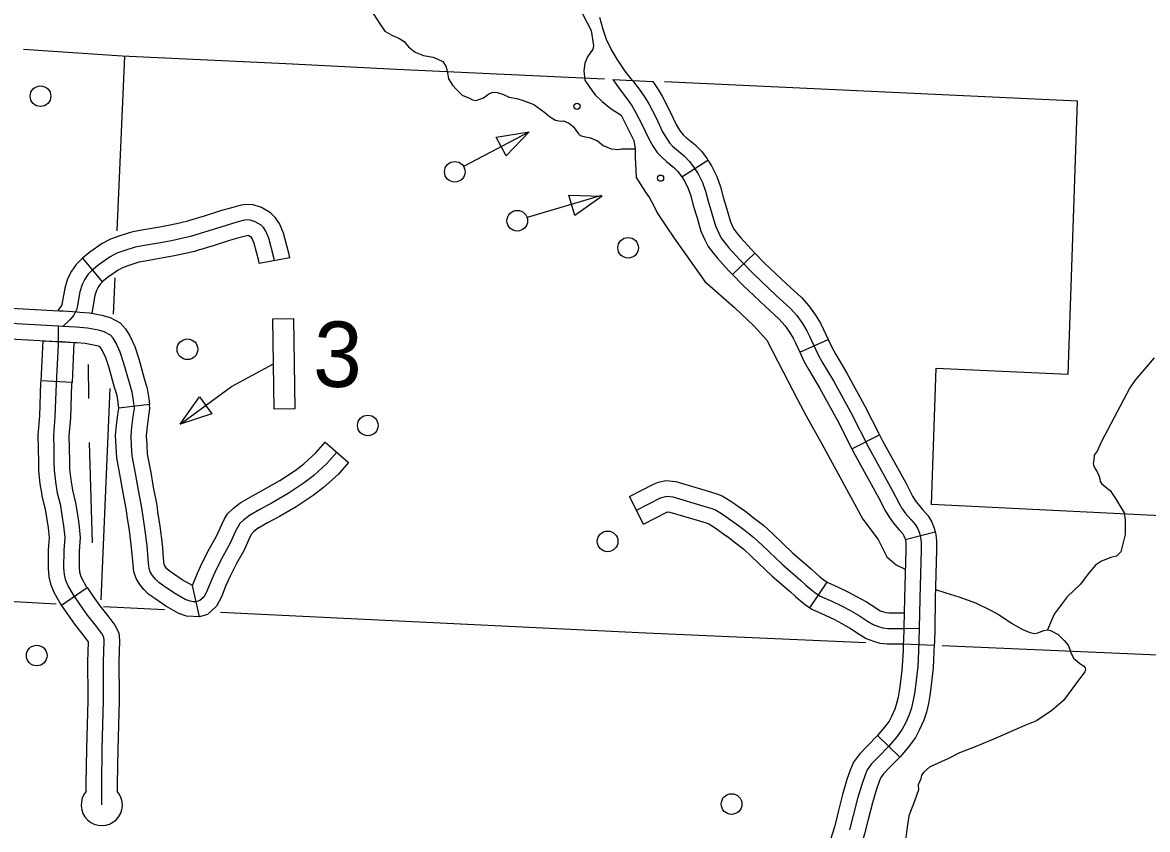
# Model space of a CAD drawing. Extents: x 653372 to 905732, y 627442 to 787275.
# Drawn here: x 699755 to 705201, y 751385 to 755293 of the extents above; entities that cross this region are included whole.
import ezdxf

# ---------------------------------------------------------------- set-up
doc = ezdxf.new("R2010")
doc.units = 0
for name, color, linetype in [('31', 7, 'Continuous'), ('32', 7, 'Continuous'), ('33', 7, 'Continuous'), ('35', 7, 'Continuous'), ('45', 7, 'Continuous'), ('5', 7, 'Continuous'), ('56', 7, 'Continuous'), ('6', 7, 'Continuous')]:
    doc.layers.add(name, color=color, linetype=linetype)

msp = doc.modelspace()

# ---------------------------------------------------------------- linework, layer by layer
at = {"layer": '31'}
for p, q in [((700018.9, 753741.3), (700018.9, 753741.3)), ((699994.9, 753549.8), (699845.1, 753557.1)), ((699994.9, 753549.8), (699994.9, 753549.8)), ((700369.9, 753442.9), (700220.9, 753425.8)), ((701221, 753261.2), (701333.7, 753162.2)), ((699944.5, 752471.2), (700067.8, 752556.6)), ((700611.3, 752414), (700578.1, 752565.9))]:
    msp.add_line(p, q, dxfattribs=at)
for points in [[(699501.8, 753919.4), (699641.5, 753913), (699931.6, 753896.4), (699952.7, 753896.2), (700020.2, 753891.8), (700032.3, 753890.7)], [(700032.3, 753890.7), (700079.2, 753886.4), (700139.9, 753875.5), (700179.4, 753864.9), (700228.6, 753837.7), (700254.4, 753808.6), (700274.1, 753775.8), (700298.6, 753723), (700317.7, 753663.9), (700344.5, 753568.2), (700359.3, 753519.9), (700366.5, 753472.7), (700369.9, 753442.9)], [(699929, 753821.5), (699637.6, 753838.1), (699423.8, 753847.8), (699374.8, 753852.6), (699363, 753857.6)], [(700139.1, 751504.1), (700138.7, 751606.3), (700141.4, 751773.3), (700147.3, 752009.2), (700147.1, 752196.1), (700150.2, 752298.1), (700148.4, 752315.6), (700138.5, 752334.4), (700108.3, 752373.7), (700069.2, 752423.6), (700035.8, 752471), (700001.4, 752520.8), (699976, 752565.6), (699965.2, 752590.3), (699959.1, 752619.5), (699955.4, 752652.2), (699956.8, 752736.2), (699961, 752798.8), (699955.7, 752855.8), (699946.8, 752907.2), (699940, 752951.5), (699924.5, 753013.4), (699915.7, 753068.3), (699909.3, 753125.3), (699909.2, 753161.3), (699907.9, 753232.5), (699906.2, 753292.9), (699913.6, 753383.2), (699919.6, 753544.3), (699928.7, 753732.1), (699929, 753821.5)], [(701277.3, 753211.7), (701228.9, 753156.5), (701164.8, 753098.5), (701117.8, 753063), (701040.8, 753011.2), (700963.2, 752966.7), (700904.8, 752934.8), (700853.3, 752905.5), (700826.4, 752885), (700807, 752865.9), (700798.4, 752852.2), (700787, 752829.5), (700760.7, 752772.1), (700725.1, 752707.5), (700692.9, 752644.2), (700670.9, 752596.5), (700649.7, 752542.9), (700634, 752512.2), (700612.9, 752493.2), (700596.3, 752487.9), (700583.2, 752486.7), (700566.1, 752491.3), (700543.3, 752499.4), (700488.1, 752530.6), (700438.3, 752564.9), (700415, 752581.2), (700398.2, 752597.3), (700384.8, 752614.1), (700373.8, 752632.5), (700367.8, 752649.1), (700365.3, 752674.6), (700357.9, 752758.5), (700346.6, 752843.9), (700332.3, 752942.8), (700316, 753028.6), (700303.4, 753101.2), (700286.5, 753193.8), (700283.1, 753243.1), (700280.4, 753290.8), (700284.1, 753332.5), (700291.4, 753384.8), (700296.7, 753423.2), (700292.1, 753462.8), (700286, 753503.1), (700272.5, 753547), (700245.8, 753642.2), (700228.6, 753695.7), (700207.8, 753740.6), (700193.7, 753764), (700181, 753778.3), (700151.2, 753794.8), (700123.5, 753802.2), (700069.2, 753812), (700014.3, 753817), (699949.8, 753821.2), (699929, 753821.5)], [(700018.9, 753741.3), (700008.5, 753742.2), (699946.9, 753746.3), (699926.5, 753746.5), (699633.8, 753763.2), (699495, 753769.5)], [(699845.1, 753557.1), (699854.5, 753750.6), (700004.3, 753742.6)], [(700004.3, 753742.6), (699994.9, 753549.8)], [(700220.9, 753425.8), (700217.8, 753452.8), (700212.7, 753486.4), (700200.5, 753525.9), (700174, 753620.6), (700158.6, 753668.3), (700141.4, 753705.4), (700133.2, 753719), (700122.9, 753724.7), (700107.1, 753729), (700059.1, 753737.6), (700018.9, 753741.3)], [(699848.3, 753014.9), (699841.4, 753058.1), (699834.3, 753121), (699834.2, 753160.5), (699832.9, 753230.7), (699831.1, 753294.9), (699838.7, 753387.6), (699844.6, 753547.6), (699845.1, 753557.1)], [(699996.4, 753038.7), (699990, 753078.4), (699984.3, 753129.6), (699984.2, 753162.1), (699982.9, 753234.2), (699981.3, 753290.9), (699988.5, 753378.8), (699994.5, 753541.1), (699994.9, 753549.8)], [(700262.5, 752901.4), (700258.3, 752930.4), (700242.2, 753015.2), (700229.6, 753088), (700212, 753184.4), (700208.2, 753238.4), (700205.2, 753292), (700209.6, 753341), (700217.1, 753395.1), (700221.1, 753424), (700220.9, 753425.8)], [(700411, 752922.8), (700406.3, 752955.1), (700389.8, 753042), (700377.3, 753114.3), (700361, 753203.1), (700357.9, 753247.8), (700355.6, 753289.6), (700358.7, 753324), (700365.7, 753374.5), (700372.3, 753422.4), (700369.9, 753443)], [(700806.8, 752964.4), (700811.8, 752968.2), (700868.3, 753000.3), (700926.6, 753032.2), (701001.2, 753074.9), (701074.3, 753124.1), (701117, 753156.4), (701175.4, 753209.2), (701221, 753261.2)], [(701333.7, 753162.2), (701282.4, 753103.8), (701212.7, 753040.7), (701161.4, 753002), (701080.4, 752947.4), (700999.8, 752901.3), (700941.3, 752869.4), (700894.8, 752842.8), (700897.9, 752845.2)], [(699944.5, 752471.2), (699937.8, 752480.9), (699908.9, 752532), (699893.4, 752567.4), (699884.9, 752607.7), (699880.4, 752648.6), (699881.8, 752739.4), (699885.8, 752797.9), (699881.3, 752846), (699872.8, 752895.1), (699866.4, 752936.6), (699851, 752998.3), (699848.3, 753014.9)], [(700067.8, 752556.6), (700065, 752560.7), (700043.2, 752599.3), (700037, 752613.3), (700033.2, 752631.4), (700030.5, 752655.7), (700031.7, 752733.1), (700036.2, 752799.7), (700030.1, 752865.7), (700020.9, 752919.2), (700013.7, 752966.3), (699998, 753028.5), (699996.4, 753038.7)], [(700578.1, 752565.9), (700602, 752626), (700625.4, 752676.9), (700658.9, 752742.6), (700693.7, 752805.8), (700719.4, 752862), (700733, 752889), (700748.2, 752913.2), (700777.2, 752941.7), (700806.8, 752964.4)], [(700611.3, 752414), (700549.1, 752418.2), (700543.7, 752419.6), (700512.1, 752430.9), (700448.3, 752466.9), (700395.5, 752503.3), (700367.2, 752523), (700342.7, 752546.6), (700323, 752571.3), (700305.8, 752600.1), (700294.1, 752632.2), (700290.6, 752667.6), (700283.4, 752750.3), (700272.3, 752833.6), (700262.5, 752901.4)], [(700578.1, 752565.9), (700527.9, 752594.2), (700481, 752626.5), (700462.7, 752639.3), (700453.7, 752647.9), (700446.6, 752656.9), (700441.9, 752664.8), (700441.5, 752665.9), (700439.9, 752681.5), (700432.5, 752766.7), (700420.8, 752854.2), (700411, 752922.8)], [(700897.9, 752845.2), (700875.7, 752828.2), (700865.8, 752818.5), (700863.8, 752815.3), (700854.7, 752797.1), (700827.7, 752738.3), (700791.4, 752672.4), (700760.4, 752611.5), (700739.9, 752566.9), (700718, 752511.9), (700694.5, 752465.8), (700651.1, 752426.6), (700611.3, 752414)], [(700067.8, 752556.6), (700097.3, 752513.9), (700129.5, 752468.3), (700167.6, 752419.6), (700201.9, 752375), (700221.5, 752337.6), (700225.3, 752300.8), (700222.1, 752195), (700222.3, 752032.1)], [(700072.3, 752031.9), (700072.1, 752197.2), (700075, 752294), (700049.1, 752327.7), (700009, 752378.8), (699974.3, 752428.1), (699944.5, 752471.2)], [(700063.8, 751570), (700063.7, 751606.7), (700066.4, 751774.9), (700072.3, 752010.1), (700072.3, 752031.9)], [(700222.3, 752032.1), (700222.3, 752008.3), (700216.3, 751771.8), (700213.7, 751605.8), (700213.8, 751570.6)]]:
    msp.add_lwpolyline(points, dxfattribs=at)
msp.add_arc((700139.1, 751504.1), 100, 138.822, 41.6419, dxfattribs=at)
at = {"layer": '32'}
for p, q in [((702612.7, 755016.6), (702806.1, 755007.6)), ((702946.6, 754544.6), (703072.2, 754626.6)), ((703192.3, 754072.4), (703300.7, 754176)), ((703518.4, 753696), (703654.8, 753758.3)), ((703769.6, 753228.3), (703903.3, 753296.2)), ((704027.9, 752788.7), (704173, 752826.7)), ((704018.7, 752283.5), (704168.6, 752277.1)), ((703893.5, 751840), (704001.3, 751735.6))]:
    msp.add_line(p, q, dxfattribs=at)
for points in [[(702612.7, 755016.6), (702648.1, 754966.1), (702684.5, 754919.4), (702705.6, 754887.1), (702721.5, 754861.3), (702755, 754797.2), (702787.2, 754728.7), (702808.8, 754691.9), (702827.7, 754663.7), (702849.4, 754639.8), (702872.8, 754620), (702907.4, 754591.1), (702927.1, 754571.3), (702945.4, 754546.5), (702946.6, 754544.6)], [(702707.3, 755012.2), (702745.6, 754963), (702768.9, 754927.3), (702786.7, 754898.4), (702822.2, 754830.5), (702853.6, 754763.7), (702872.4, 754731.8), (702886.9, 754710.1), (702901.6, 754693.9), (702921.1, 754677.4), (702958.1, 754646.4), (702984.2, 754620.3), (703007.1, 754589.3), (703025.9, 754560.3), (703047.4, 754518.2), (703061.8, 754475.2), (703074.6, 754426.7), (703092.5, 754367.9), (703109.5, 754307.6), (703125.1, 754272.2), (703137.1, 754249), (703156.1, 754224.7), (703174.6, 754201.3), (703228.1, 754143.5), (703294.8, 754073.6), (703402.2, 753972.9), (703472.1, 753908), (703503.5, 753873.1), (703531.2, 753834.8), (703551.9, 753800.3), (703565.3, 753773.8), (703605.2, 753686.6), (703626.3, 753647.4), (703680.2, 753557.5)], [(702806.1, 755007.6), (702832.2, 754967.5), (702852, 754935.5), (702889.4, 754863.8), (702920, 754798.8), (702935.9, 754771.7), (702946.1, 754756.4), (702953.8, 754748), (702969.4, 754734.8), (703008.9, 754701.8), (703041.3, 754669.3), (703068.7, 754632), (703072.2, 754626.6)], [(703072.2, 754626.6), (703090.9, 754598), (703116.8, 754547.3), (703133.8, 754496.6), (703146.7, 754447.2), (703164.5, 754389), (703180.2, 754333), (703192.8, 754304.6), (703200.5, 754289.7), (703215, 754271), (703231.6, 754250.2), (703282.7, 754194.9), (703300.7, 754176)], [(702946.6, 754544.6), (702960.9, 754522.7), (702978.1, 754489), (702989.9, 754453.7), (703002.4, 754406.2), (703020.6, 754346.8), (703038.7, 754282.2), (703057.4, 754239.8), (703073.6, 754208.4), (703097.1, 754178.3), (703117.6, 754152.5), (703173.4, 754092.1), (703192.3, 754072.4)], [(703300.7, 754176), (703347.6, 754126.9), (703453.3, 754027.7), (703525.6, 753960.7), (703561.9, 753920.3), (703593.8, 753876.2), (703617.6, 753836.6), (703632.9, 753806.4), (703654.8, 753758.3)], [(703192.3, 754072.4), (703242, 754020.3), (703351, 753918.1), (703418.6, 753855.3), (703445, 753826), (703468.5, 753793.5), (703486.2, 753764), (703497.7, 753741.3), (703518.4, 753696)], [(703654.8, 753758.3), (703672.4, 753720), (703691.5, 753684.5), (703745.2, 753594.8), (703831, 753438.7), (703903.3, 753296.2)], [(703518.4, 753696), (703538, 753653.1), (703561.1, 753610.3), (703615.1, 753520.1), (703698.4, 753368.6), (703769.6, 753228.3)], [(703680.2, 753557.5), (703764.7, 753403.6), (703851.6, 753232.4), (703965.6, 753027.7), (703998.2, 752963.4), (704014.1, 752937.1), (704030.1, 752914.7), (704055.1, 752885.8), (704077.9, 752859.8), (704088.8, 752840.5), (704097.4, 752819.5), (704102.5, 752799.8), (704105.3, 752776.7), (704105.3, 752738.5), (704098.8, 752504), (704096.2, 752359.5), (704094.3, 752295.1), (704092.3, 752248), (704088.9, 752172.7), (704086.4, 752148.3), (704079, 752092.7), (704072.9, 752044), (704067.3, 752010.8), (704058.2, 751974.2), (704047.4, 751940.6), (704028.9, 751899.2), (704013.7, 751870.4), (703987.3, 751833.3), (703948, 751788.4), (703898.1, 751737), (703864.9, 751702.3), (703844.5, 751674.2), (703832.4, 751645.1), (703817.4, 751603), (703796.9, 751534.6), (703776, 751452.4), (703759, 751383.9)], [(703903.3, 753296.2), (703917.8, 753267.7), (704031.8, 753062.9), (704063.8, 752999.8), (704076.8, 752978.3), (704089.1, 752961.2), (704111.7, 752935), (704139.4, 752903.4), (704156.4, 752873.2), (704168.7, 752843.3), (704173, 752826.7)], [(703769.6, 753228.3), (703785.3, 753197.2), (703899.4, 752992.5), (703932.5, 752927.1), (703951.4, 752895.8), (703971.1, 752868.3), (703998.5, 752836.5), (704016.4, 752816.1), (704021.2, 752807.7), (704026.1, 752795.7), (704027.9, 752788.7)], [(704173, 752826.7), (704176.4, 752813.8), (704180.3, 752781.1), (704180.3, 752737.5), (704173.8, 752502.2), (704171.2, 752357.7), (704169.2, 752292.4), (704168.6, 752277.1)], [(704027.9, 752788.7), (704028.7, 752785.8), (704030.3, 752772.2), (704030.3, 752739.5), (704023.9, 752505.7), (704021.2, 752361.3), (704019.3, 752297.8), (704018.7, 752283.5)], [(704018.7, 752283.5), (704017.4, 752251.3), (704014.1, 752178.2), (704011.9, 752157), (704004.6, 752102.3), (703998.7, 752054.9), (703993.9, 752026.2), (703986, 751994.8), (703977.3, 751967.5), (703961.5, 751932.1), (703949.7, 751909.9), (703928.3, 751879.8), (703892.8, 751839.3), (703893.6, 751840.1)], [(704168.6, 752277.1), (704167.2, 752244.7), (704163.7, 752167.3), (704160.9, 752139.6), (704153.4, 752083.1), (704147.2, 752033.1), (704140.8, 751995.4), (704130.4, 751953.7), (704117.6, 751913.8), (704096.4, 751866.3), (704077.6, 751831), (704046.2, 751786.7), (704003.1, 751737.5), (704001.2, 751735.6)], [(703893.5, 751840), (703844.1, 751789), (703807.1, 751750.5), (703778.5, 751711), (703762.4, 751672.1), (703746.1, 751626.4), (703724.6, 751554.6), (703703.3, 751470.6), (703686.6, 751403.3), (703667.1, 751336.1)], [(704001.3, 751735.6), (703952.1, 751684.9), (703922.6, 751654.1), (703910.4, 751637.3), (703902.4, 751618.1), (703888.6, 751579.6), (703869.2, 751514.6), (703848.8, 751434.1), (703831.5, 751364.4), (703811.2, 751294.5)]]:
    msp.add_lwpolyline(points, dxfattribs=at)
at = {"layer": '33'}
msp.add_lwpolyline([(702707.3, 755012.2), (702673.1, 755056.3), (702634.3, 755114.4), (702605.1, 755162.9), (702582.4, 755210.6), (702566, 755258), (702549.3, 755316.9)], dxfattribs=at)
at = {"layer": '35'}
for points in [[(702437, 755387.9), (702466.6, 755334.3), (702508.1, 755253.7), (702518.9, 755178.9), (702515.6, 755163), (702489.8, 755126.5), (702477.1, 755095.8), (702472.2, 755058.8), (702477.2, 755013.7), (702516.4, 754956.8), (702526.7, 754942.9)], [(701438.1, 755358.1), (701485.1, 755285.8), (701509.7, 755249.9), (701542.9, 755231.4), (701577.6, 755216.8), (701602.8, 755199.8), (701623.7, 755174.9), (701656.6, 755148.2), (701696.7, 755133.5), (701743.8, 755125.3), (701765.1, 755115.2), (701789.1, 755103.7), (701805.8, 755077.5), (701813.1, 755048.9), (701817.6, 755019), (701837, 754988.7), (701856.6, 754967.8), (701884.2, 754941.3), (701918.9, 754926.8), (701933.5, 754918.2), (701950.9, 754915), (701986.5, 754927.4), (702012.7, 754946.9), (702031.9, 754954.5), (702053.5, 754953.8), (702084.2, 754943.4), (702110.9, 754930.5), (702148.5, 754923.9), (702179.3, 754914.9), (702230.1, 754895.8), (702282.9, 754856.4), (702305.4, 754838.1), (702335.9, 754819.6), (702358.7, 754814.9), (702373.6, 754817.1), (702399, 754805.6), (702404.2, 754801.4), (702420.1, 754788.7), (702433, 754770.8), (702446.1, 754754.1), (702455.3, 754745.8), (702479.4, 754739.6), (702499.6, 754736.3), (702539, 754718.9), (702566.7, 754696.5), (702605.5, 754680.4), (702641.9, 754678), (702654.1, 754680.3), (702720.2, 754681.1)], [(702526.7, 754942.9), (702561, 754909.4), (702604.4, 754875), (702653.2, 754843.6), (702713.9, 754720.4), (702720.2, 754681.1), (702720.2, 754637), (702721.9, 754609.7)], [(702721.9, 754609.7), (702726.1, 754541.9), (702770.3, 754471.5), (702789.7, 754443.1), (702809.2, 754408.4), (702827.8, 754370.5)], [(702827.8, 754370.5), (702871.8, 754303.4), (702909.2, 754248.3), (703058, 754039.1), (703202.1, 753912.4), (703294.8, 753824), (703358.1, 753753.8), (703411.9, 753650.4), (703507.4, 753466.8), (703549.2, 753388.7), (703624.8, 753252.8), (703822.9, 752888.3), (703896.8, 752789.3), (703939.5, 752706), (703985, 752667.3), (704027.7, 752645.3)], [(705233.6, 753669.1), (705139, 753558.3), (705115.6, 753524), (704977.1, 753260.8)], [(704977.1, 753260.8), (704957.7, 753216.7), (704943.3, 753196.9), (704940.5, 753175.7), (704937.3, 753157.8), (704939.7, 753149.2), (704945.2, 753135.2), (704956.8, 753116.3), (704965.3, 753099.6), (704969.7, 753085.1), (704971.9, 753070.7), (704979, 753059.8), (704999.7, 753042.7), (705020.4, 753026.2), (705046.3, 752988.3), (705088, 752917.9), (705092.9, 752885), (705092.4, 752814.2), (705083.7, 752774), (705071.4, 752729.7), (705051.3, 752708.3), (705023.3, 752701.6), (704978.1, 752684.4), (704948.9, 752664.2), (704913.9, 752623.4), (704877, 752573.5), (704812.8, 752511.3), (704749.5, 752427.2), (704717.1, 752351.4)], [(704175, 752546.4), (704225.4, 752531.5), (704287.8, 752511.4), (704368.2, 752482.3), (704444.9, 752445.7), (704483.5, 752424.2), (704543.3, 752383.8), (704596.3, 752352.8), (704633, 752338.4), (704655.3, 752334.2), (704669.7, 752337.4), (704698.8, 752347.8), (704717.1, 752351.4), (704731, 752348.9), (704768.3, 752329.6), (704796.8, 752299.4), (704816.5, 752277), (704824.9, 752255.8), (704832.1, 752237.3), (704844.7, 752213.8), (704859.7, 752200.7), (704873.4, 752189.1), (704891.2, 752177.4), (704899.4, 752168), (704901.3, 752160.9), (704898.1, 752149.1), (704872.5, 752114.4), (704795.1, 752010.2), (704738.3, 751960.8), (704663.2, 751911.1), (704607.3, 751887.8), (704515.7, 751847.7), (704452.6, 751820.9), (704405.1, 751802), (704358.2, 751782.4), (704290.9, 751755.7), (704231.1, 751725.9), (704191.3, 751708.2), (704145.9, 751686.7), (704118.5, 751662.3), (704106.9, 751648.6), (704103.5, 751630.5), (704091.5, 751601.4), (704092.1, 751577.6), (704073.7, 751522), (704046.3, 751451.4), (704035.9, 751385.8), (704028.4, 751320.1)]]:
    msp.add_lwpolyline(points, dxfattribs=at)
at = {"layer": '45'}
for p, q in [((700045.8, 754151.8), (700141.4, 754036.2)), ((701048.5, 754152.5), (700901, 754125.1)), ((702761.2, 752864.2), (702692.8, 752997.6)), ((703565.7, 752458.7), (703650.6, 752582.4))]:
    msp.add_line(p, q, dxfattribs=at)
for points in [[(701048.5, 754152.5), (701045.3, 754169.9), (701019.2, 754272.8), (700998.5, 754318.8), (700979.7, 754347.4), (700956, 754370.8), (700912.7, 754396), (700871.1, 754410.3), (700833.1, 754411.5), (700807.4, 754406.6), (700773.1, 754397.5), (700714.1, 754380.3), (700634.8, 754355.1), (700563.9, 754334.1)], [(700974.8, 754138.8), (700972, 754153.9), (700948.1, 754248), (700932.5, 754282.6), (700921.4, 754299.6), (700910, 754310.8), (700881.4, 754327.5), (700857.4, 754335.7), (700839.1, 754336.3), (700824, 754333.4), (700793.1, 754325.2), (700736, 754308.6), (700656.9, 754283.5), (700567.7, 754257), (700518.4, 754245.2), (700476.4, 754235.6), (700422.8, 754226.3), (700335.7, 754211.5), (700300.5, 754205), (700250, 754189), (700212.1, 754175.2), (700179.9, 754157.8), (700126.3, 754121), (700091.3, 754092.1), (700073.2, 754073.5), (700056.7, 754049.8), (700043.4, 754023.5), (700032.3, 753988), (700019.2, 753914.2), (700017.2, 753900.9), (700003.1, 753874.7), (699984.9, 753852.7), (699949.8, 753821.2)], [(700563.9, 754334.1), (700548.3, 754329.4), (700501.3, 754318.2), (700461.7, 754309.1), (700410.1, 754300.3), (700322.6, 754285.3), (700282.3, 754277.9), (700225.8, 754260), (700181.2, 754243.7), (700140.8, 754221.9), (700081.1, 754181), (700045.8, 754151.8)], [(700901, 754125.1), (700898.7, 754137.8), (700877.1, 754223.1), (700866.6, 754246.4), (700863.5, 754251.1), (700850, 754259), (700844.3, 754260.9), (700840.7, 754260.2), (700813.2, 754252.9), (700757.8, 754236.8), (700678.9, 754211.8), (700606.6, 754190.3)], [(700606.6, 754190.3), (700587.1, 754184.5), (700535.4, 754172.1), (700491.1, 754162), (700435.5, 754152.4), (700348.8, 754137.6), (700318.6, 754132.1), (700274.2, 754118), (700242.9, 754106.6), (700219, 754093.7), (700171.5, 754061.1), (700141.3, 754036.2)], [(700045.8, 754151.8), (700040.3, 754147.3), (700015.2, 754121.3), (699992.1, 754088.4), (699973.6, 754051.8), (699959.3, 754005.7), (699945.3, 753926.5), (699945, 753925.1), (699940.5, 753916.7), (699923.8, 753896.5)], [(700142.2, 754036.9), (700131.2, 754025.6), (700121.2, 754011.2), (700113.1, 753995.2), (700105.3, 753970.2), (700090.2, 753884.5)], [(702692.8, 752997.6), (702810.2, 753057.9), (702833.5, 753066.4), (702868.6, 753074.5), (702917, 753070.3), (703074.8, 753022.9), (703111.6, 753011.9), (703142.6, 753000.5), (703184.6, 752974.8), (703252.4, 752927.7)], [(702727, 752930.9), (702840.3, 752989.1), (702854.8, 752994.4), (702873.8, 752998.7), (702902.9, 752996.2), (703053.3, 752951.1), (703087.9, 752940.7), (703109.8, 752932.6), (703143.6, 752911.9), (703210.3, 752865.6), (703246.4, 752837.4), (703295.3, 752799), (703336, 752761.7), (703434.1, 752667.7), (703522.5, 752591.3), (703546.4, 752568.5), (703566.4, 752551.5), (703590.5, 752532.7), (703613, 752517.2), (703672.1, 752490.8), (703719, 752468.1), (703756.9, 752448.1), (703801.3, 752423), (703845.5, 752394.5), (703872.9, 752377.3), (703898.1, 752367.5), (703920, 752361.1), (703944.5, 752358.7), (704028.2, 752358.7), (704096.2, 752359.5)], [(702761.2, 752864.2), (702870.4, 752920.2), (702876.2, 752922.3), (702879.1, 752923), (702888.7, 752922.2), (703031.7, 752879.2), (703064.2, 752869.5), (703077, 752864.8), (703102.6, 752849.1), (703166.9, 752804.5)], [(703252.4, 752927.7), (703254.8, 752926), (703292.6, 752896.5), (703343.9, 752856.3), (703387.3, 752816.4), (703484.6, 752723.2), (703573, 752646.9), (703596.7, 752624.2), (703613.8, 752609.6), (703634.8, 752593.2), (703650.6, 752582.4)], [(703165.8, 752805.2), (703200.2, 752778.4), (703246.7, 752741.8), (703284.7, 752707), (703383.6, 752612.2), (703472.1, 752535.8), (703496.2, 752512.8), (703519, 752493.3), (703546.1, 752472.1), (703565.7, 752458.7)], [(703649.8, 752582.9), (703703.7, 752558.8), (703752.8, 752535), (703792.9, 752513.9), (703840, 752487.2), (703885.8, 752457.8), (703906.8, 752444.6), (703922.2, 752438.6), (703934.3, 752435.1), (703948.2, 752433.7), (704022.5, 752433.7)], [(703565.7, 752458.7), (703576.2, 752451.5), (703640.4, 752422.8), (703685.1, 752401.2), (703720.9, 752382.3), (703762.5, 752358.7), (703805.3, 752331.3), (703839, 752310), (703873.9, 752296.4), (703905.8, 752287.2), (703940.9, 752283.8), (704018.7, 752283.7)]]:
    msp.add_lwpolyline(points, dxfattribs=at)
at = {"layer": '5'}
for points in [[(700248.3, 755129.1), (700211.5, 754283)], [(700201.6, 754055.8), (700193.9, 753880)], [(700178.3, 753520.7), (700133.8, 752497.7)], [(699917.8, 752475.5), (698733.7, 752542.6)], [(700442.2, 752448.4), (700147.4, 752462.6)], [(703837.8, 752289.6), (702772.3, 752335.8), (700713.5, 752435.3)], [(705400.8, 752221.9), (704206.2, 752273.6)]]:
    msp.add_lwpolyline(points, dxfattribs=at)
at = {"layer": '56'}
for p, q in [((702048.3, 754737.2), (702207.4, 754763.5)), ((702095.9, 754647), (702048.3, 754737.2)), ((702207.4, 754763.5), (702095.9, 754647)), ((702399.2, 754456.6), (702560.4, 754450.9)), ((702428.1, 754358.8), (702399.2, 754456.6)), ((702560.4, 754450.9), (702428.1, 754358.8)), ((700518.2, 753348.3), (700611.7, 753479.8)), ((700611.7, 753479.8), (700671.9, 753397.4)), ((700671.9, 753397.4), (700518.2, 753348.3))]:
    msp.add_line(p, q, dxfattribs=at)
for points in [[(701892.1, 754597.2), (702207.4, 754763.5)], [(702199.2, 754350.3), (702559, 754456.3)], [(700072.6, 753636.6), (700074.9, 753472)], [(700518.2, 753348.3), (700766.4, 753529.8), (700970.2, 753639.3)], [(700077.8, 753259.2), (700092, 752773.6)]]:
    msp.add_lwpolyline(points, dxfattribs=at)
msp.add_lwpolyline([(700967.2, 753858), (701067.2, 753859.4), (701073.1, 753421.9), (700973.1, 753420.5)], close=True, dxfattribs=at)
for centre, radius in [((699842.2, 754935.7), 50), ((702439.7, 754886.7), 15), ((701847.8, 754569.6), 50), ((702843.8, 754538.9), 15), ((702150.1, 754332.6), 50), ((702686.8, 754201.6), 50), ((700553.6, 753710.4), 50), ((701426.6, 753341.3), 50), ((702587.6, 752780.3), 50), ((699824.1, 752227.4), 50), ((703187.5, 751508.1), 50)]:
    msp.add_circle(centre, radius, dxfattribs=at)
at = {"layer": '6'}
for points in [[(706340.2, 758809.2), (706303.8, 758153.3), (706958.8, 758122.1), (706928.1, 757443.5), (706792.6, 754159.1), (706765, 753494), (705455.8, 753556.9), (705428, 752895.9), (704155, 752957.9), (704178.2, 753618.8), (704816.7, 753589.4), (704862.8, 754911.4), (702862.7, 755004.9)], [(702573.1, 755018.5), (701566.3, 755065.5), (701029.9, 755091.8), (700237.3, 755129.6), (699759.7, 755161.1)]]:
    msp.add_lwpolyline(points, dxfattribs=at)

# ---------------------------------------------------------------- texts
at = {"layer": '56'}
msp.add_text('3', height=316.8, rotation=358.28, dxfattribs=at).set_placement((701159.4, 753531.4))

doc.saveas('drawing.dxf')
